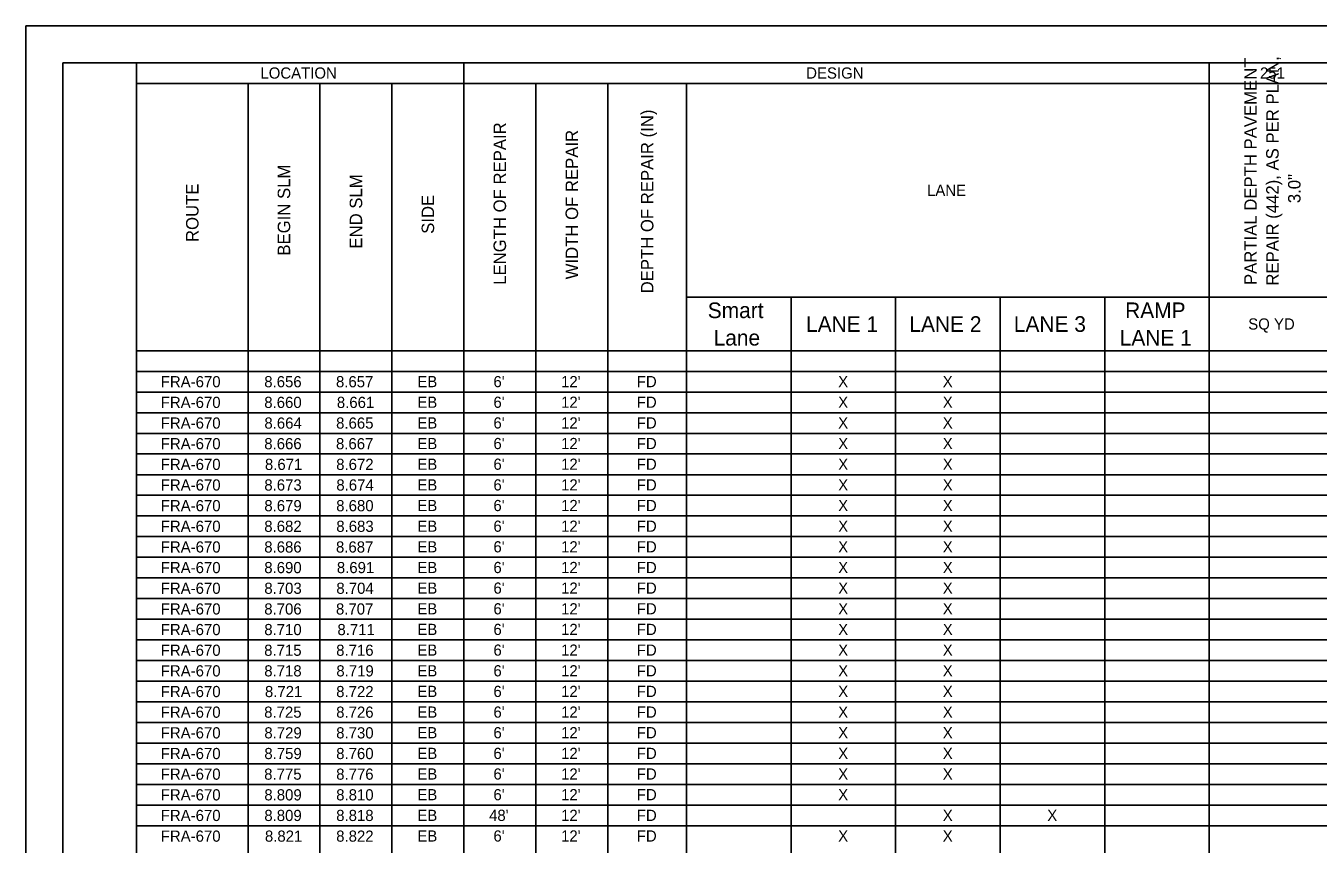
# Model space of a CAD drawing. Extents: x 0 to 34, y 0 to 22.
# Drawn here: x 0 to 17.5, y 10.92 to 22 of the extents above; entities that cross this region are included whole.
import ezdxf

# ---------------------------------------------------------------- set-up
doc = ezdxf.new("R2010")
doc.units = 0
for name, color, linetype in [('SH_Border', 7, 'Continuous'), ('SH_Cut_Line', 7, 'Continuous'), ('SH_Text', 7, 'Continuous')]:
    doc.layers.add(name, color=color, linetype=linetype)

msp = doc.modelspace()

# ---------------------------------------------------------------- linework, layer by layer
at = {"layer": 'SH_Border'}
for points in [[(0.5, 21.5), (1.5, 21.5), (1.5, 0.5), (0.5, 0.5)], [(1.5, 21.5), (33.5, 21.5), (33.5, 0.5), (1.5, 0.5)]]:
    msp.add_lwpolyline(points, close=True, dxfattribs=at)
at = {"layer": 'SH_Cut_Line'}
msp.add_lwpolyline([(0, 0), (34, 0), (34, 22), (0, 22)], close=True, dxfattribs=at)
at = {"layer": 'SH_Text'}
for p, q in [((1.5, 21.5), (32, 21.5)), ((5.931, 21.5), (5.931, 1.388)), ((16.024, 21.5), (16.024, 0.5)), ((1.5, 21.22), (32, 21.22)), ((1.5, 21.22), (1.5, 1.388)), ((3.008, 21.22), (3.008, 1.388)), ((3.982, 21.22), (3.982, 1.388)), ((4.956, 21.22), (4.956, 1.388)), ((6.905, 21.22), (6.905, 1.388)), ((7.879, 21.22), (7.879, 1.388)), ((8.946, 21.22), (8.946, 1.388)), ((8.946, 18.326), (23.028, 18.326)), ((10.361, 18.326), (10.361, 1.388)), ((11.777, 18.326), (11.777, 1.388)), ((13.193, 18.326), (13.193, 1.388)), ((14.608, 18.326), (14.608, 1.388)), ((1.5, 17.603), (32, 17.603)), ((1.5, 17.323), (32, 17.323)), ((1.5, 17.043), (32, 17.043)), ((1.5, 16.764), (32, 16.764)), ((1.5, 16.484), (32, 16.484)), ((1.5, 16.205), (32, 16.205)), ((1.5, 15.925), (32, 15.925)), ((1.5, 15.646), (32, 15.646)), ((1.5, 15.366), (32, 15.366)), ((1.5, 15.087), (32, 15.087)), ((1.5, 14.807), (32, 14.807)), ((1.5, 14.527), (32, 14.527)), ((1.5, 14.248), (32, 14.248)), ((1.5, 13.968), (32, 13.968)), ((1.5, 13.689), (32, 13.689)), ((1.5, 13.409), (32, 13.409)), ((1.5, 13.13), (32, 13.13)), ((1.5, 12.85), (32, 12.85)), ((1.5, 12.57), (32, 12.57)), ((1.5, 12.291), (32, 12.291)), ((1.5, 12.011), (32, 12.011)), ((1.5, 11.732), (32, 11.732)), ((1.5, 11.452), (32, 11.452)), ((1.5, 11.173), (32, 11.173))]:
    msp.add_line(p, q, dxfattribs=at)
for points in [[(1.5, 21.5), (1.5, 21.5), (1.5, 21.5), (1.5, 21.5)], [(1.5, 21.5), (1.5, 21.5), (1.5, 21.5), (1.5, 21.5)], [(1.5, 21.5), (1.5, 21.5), (1.5, 20.776), (1.5, 20.776)], [(1.5, 21.5), (1.5, 21.5), (1.5, 21.22), (1.5, 21.22)], [(1.5, 21.5), (1.5, 21.5), (1.5, 21.22), (1.5, 21.22)], [(1.5, 21.5), (1.5, 21.5), (1.5, 21.22), (1.5, 21.22)], [(1.5, 21.5), (1.5, 21.5), (1.5, 21.22), (1.5, 21.22)], [(1.5, 21.5), (1.5, 21.5), (1.5, 21.22), (1.5, 21.22)], [(1.5, 21.5), (1.5, 21.5), (1.5, 21.22), (1.5, 21.22)], [(1.5, 21.5), (1.5, 21.5), (1.5, 21.22), (1.5, 21.22)], [(1.5, 21.5), (1.5, 21.5), (1.5, 21.22), (1.5, 21.22)], [(1.5, 21.5), (1.5, 21.5), (1.5, 21.22), (1.5, 21.22)], [(1.5, 21.5), (1.5, 21.5), (1.5, 21.22), (1.5, 21.22)], [(1.5, 21.5), (1.5, 21.5), (1.5, 21.22), (1.5, 21.22)], [(1.5, 21.5), (1.5, 21.5), (1.5, 21.22), (1.5, 21.22)], [(1.5, 21.5), (1.5, 21.5), (1.5, 21.22), (1.5, 21.22)], [(1.5, 21.5), (1.5, 21.5), (1.5, 21.22), (1.5, 21.22)], [(1.5, 21.5), (1.5, 21.5), (1.5, 21.22), (1.5, 21.22)], [(1.5, 21.5), (1.5, 21.5), (1.5, 21.22), (1.5, 21.22)], [(1.5, 21.5), (1.5, 21.5), (1.5, 21.22), (1.5, 21.22)], [(1.5, 21.5), (1.5, 21.5), (1.5, 21.22), (1.5, 21.22)], [(1.5, 21.5), (1.5, 21.5), (1.5, 21.22), (1.5, 21.22)], [(1.5, 21.5), (1.5, 21.5), (1.5, 21.22), (1.5, 21.22)], [(1.5, 21.5), (1.5, 21.5), (1.5, 21.22), (1.5, 21.22)], [(1.5, 21.5), (1.5, 21.5), (1.5, 21.22), (1.5, 21.22)], [(1.5, 21.5), (1.5, 21.5), (1.5, 21.22), (1.5, 21.22)], [(1.5, 21.5), (1.5, 21.5), (1.5, 21.22), (1.5, 21.22)], [(1.5, 21.5), (1.5, 21.5), (1.5, 21.22), (1.5, 21.22)], [(1.5, 21.5), (1.5, 21.5), (1.5, 21.22), (1.5, 21.22)], [(1.5, 21.5), (1.5, 21.5), (1.5, 21.22), (1.5, 21.22)], [(1.5, 21.5), (1.5, 21.5), (1.5, 21.22), (1.5, 21.22)], [(1.5, 21.5), (1.5, 21.5), (1.5, 21.22), (1.5, 21.22)], [(1.5, 21.5), (1.5, 21.5), (1.5, 21.22), (1.5, 21.22)], [(1.5, 21.5), (1.5, 21.5), (1.5, 21.22), (1.5, 21.22)], [(1.5, 21.5), (1.5, 21.5), (1.5, 21.22), (1.5, 21.22)], [(1.5, 21.5), (1.5, 21.5), (1.5, 21.22), (1.5, 21.22)], [(1.5, 21.5), (1.5, 21.5), (1.5, 21.22), (1.5, 21.22)], [(1.5, 21.5), (1.5, 21.5), (1.5, 21.22), (1.5, 21.22)], [(1.5, 21.5), (1.5, 21.5), (1.5, 21.22), (1.5, 21.22)], [(1.5, 21.5), (1.5, 21.5), (1.5, 21.22), (1.5, 21.22)], [(1.5, 21.5), (1.5, 21.5), (1.5, 21.22), (1.5, 21.22)], [(1.5, 21.5), (1.5, 21.5), (1.5, 21.22), (1.5, 21.22)], [(1.5, 21.5), (1.5, 21.5), (1.5, 21.22), (1.5, 21.22)], [(1.5, 21.5), (1.5, 21.5), (1.5, 21.22), (1.5, 21.22)], [(1.5, 21.5), (1.5, 21.5), (1.5, 21.22), (1.5, 21.22)], [(1.5, 21.5), (1.5, 21.5), (1.5, 21.22), (1.5, 21.22)], [(1.5, 21.5), (1.5, 21.5), (1.5, 21.22), (1.5, 21.22)], [(1.5, 21.5), (1.5, 21.5), (1.5, 21.22), (1.5, 21.22)], [(1.5, 21.5), (1.5, 21.5), (1.5, 21.22), (1.5, 21.22)], [(1.5, 21.5), (1.5, 21.5), (1.5, 21.22), (1.5, 21.22)], [(1.5, 21.5), (1.5, 21.5), (1.5, 21.22), (1.5, 21.22)], [(1.5, 21.5), (1.5, 21.5), (1.5, 21.22), (1.5, 21.22)], [(1.5, 21.5), (1.5, 21.5), (1.5, 21.22), (1.5, 21.22)], [(1.5, 21.5), (1.5, 21.5), (1.5, 21.22), (1.5, 21.22)], [(1.5, 21.5), (1.5, 21.5), (1.5, 21.22), (1.5, 21.22)], [(1.5, 21.5), (1.5, 21.5), (1.5, 21.22), (1.5, 21.22)], [(1.5, 21.5), (1.5, 21.5), (1.5, 21.22), (1.5, 21.22)], [(1.5, 21.5), (1.5, 21.5), (1.5, 21.22), (1.5, 21.22)], [(1.5, 21.5), (1.5, 21.5), (1.5, 21.22), (1.5, 21.22)], [(1.5, 21.5), (1.5, 21.5), (1.5, 21.22), (1.5, 21.22)], [(1.5, 21.5), (1.5, 21.5), (1.5, 21.22), (1.5, 21.22)], [(1.5, 21.5), (1.5, 21.5), (1.5, 21.22), (1.5, 21.22)], [(1.5, 21.5), (1.5, 21.5), (1.5, 21.22), (1.5, 21.22)], [(1.5, 21.5), (1.5, 21.5), (1.5, 21.22), (1.5, 21.22)], [(1.5, 21.5), (1.5, 21.5), (1.5, 21.22), (1.5, 21.22)], [(1.5, 21.5), (1.5, 21.5), (1.5, 21.22), (1.5, 21.22)], [(1.5, 21.5), (1.5, 21.5), (1.5, 21.22), (1.5, 21.22)], [(1.5, 21.5), (1.5, 21.5), (1.5, 21.22), (1.5, 21.22)], [(1.5, 21.5), (1.5, 21.5), (1.5, 21.22), (1.5, 21.22)], [(1.5, 21.5), (1.5, 21.5), (1.5, 21.22), (1.5, 21.22)], [(1.5, 21.5), (1.5, 21.5), (1.5, 21.22), (1.5, 21.22)], [(1.5, 21.5), (1.5, 21.5), (1.5, 21.22), (1.5, 21.22)], [(1.5, 21.5), (1.5, 21.5), (1.5, 21.22), (1.5, 21.22)], [(1.5, 21.5), (1.5, 21.5), (1.5, 21.22), (1.5, 21.22)], [(1.5, 21.5), (1.5, 21.5), (1.5, 21.22), (1.5, 21.22)], [(1.5, 21.5), (1.5, 21.5), (1.5, 21.22), (1.5, 21.22)], [(1.5, 21.5), (1.5, 21.5), (1.5, 21.22), (1.5, 21.22)], [(1.5, 21.5), (1.5, 21.5), (1.5, 21.22), (1.5, 21.22)], [(1.5, 21.5), (1.5, 21.5), (1.5, 21.22), (1.5, 21.22)], [(1.5, 21.5), (1.5, 21.5), (1.5, 21.22), (1.5, 21.22)], [(1.5, 21.5), (1.5, 21.5), (1.5, 21.22), (1.5, 21.22)], [(1.5, 21.5), (1.5, 21.5), (1.5, 21.22), (1.5, 21.22)], [(1.5, 21.5), (1.5, 21.5), (1.5, 21.22), (1.5, 21.22)], [(1.5, 21.5), (1.5, 21.5), (1.5, 21.22), (1.5, 21.22)], [(1.5, 21.5), (1.5, 21.5), (1.5, 21.22), (1.5, 21.22)], [(1.5, 21.5), (1.5, 21.5), (1.5, 21.22), (1.5, 21.22)], [(1.5, 21.5), (1.5, 21.5), (1.5, 21.22), (1.5, 21.22)], [(1.5, 21.5), (1.5, 21.5), (1.5, 21.22), (1.5, 21.22)], [(1.5, 21.5), (1.5, 21.5), (1.5, 21.22), (1.5, 21.22)], [(1.5, 21.5), (1.5, 21.5), (1.5, 21.22), (1.5, 21.22)], [(1.5, 21.5), (1.5, 21.5), (1.5, 21.22), (1.5, 21.22)], [(1.5, 21.5), (1.5, 21.5), (1.5, 21.22), (1.5, 21.22)], [(1.5, 21.5), (1.5, 21.5), (1.5, 21.22), (1.5, 21.22)], [(1.5, 21.5), (1.5, 21.5), (1.5, 21.22), (1.5, 21.22)], [(1.5, 21.5), (1.5, 21.5), (1.5, 21.22), (1.5, 21.22)], [(1.5, 21.5), (1.5, 21.5), (1.5, 21.22), (1.5, 21.22)], [(1.5, 21.5), (1.5, 21.5), (1.5, 21.22), (1.5, 21.22)], [(1.5, 21.5), (1.5, 21.5), (1.5, 21.22), (1.5, 21.22)], [(1.5, 21.5), (1.5, 21.5), (1.5, 21.22), (1.5, 21.22)], [(1.5, 21.5), (1.5, 21.5), (1.5, 21.22), (1.5, 21.22)], [(1.5, 21.5), (1.5, 21.5), (1.5, 21.22), (1.5, 21.22)], [(1.5, 21.5), (1.5, 21.5), (1.5, 21.22), (1.5, 21.22)], [(1.5, 21.5), (1.5, 21.5), (1.5, 21.22), (1.5, 21.22)], [(1.5, 21.5), (1.5, 21.5), (1.5, 21.22), (1.5, 21.22)], [(1.5, 21.5), (1.5, 21.5), (1.5, 21.22), (1.5, 21.22)], [(1.5, 21.5), (1.5, 21.5), (1.5, 21.22), (1.5, 21.22)], [(1.5, 21.5), (1.5, 21.5), (1.5, 21.22), (1.5, 21.22)], [(1.5, 21.5), (1.5, 21.5), (1.5, 21.22), (1.5, 21.22)], [(1.5, 21.5), (1.5, 21.5), (1.5, 21.22), (1.5, 21.22)], [(1.5, 21.5), (1.5, 21.5), (1.5, 21.22), (1.5, 21.22)], [(1.5, 21.5), (1.5, 21.5), (1.5, 21.22), (1.5, 21.22)], [(1.5, 21.5), (1.5, 21.5), (1.5, 21.22), (1.5, 21.22)], [(1.5, 21.5), (1.5, 21.5), (1.5, 21.22), (1.5, 21.22)], [(1.5, 21.5), (1.5, 21.5), (1.5, 21.22), (1.5, 21.22)], [(1.5, 21.5), (1.5, 21.5), (1.5, 21.22), (1.5, 21.22)], [(1.5, 21.5), (1.5, 21.5), (1.5, 21.22), (1.5, 21.22)], [(1.5, 21.5), (1.5, 21.5), (1.5, 21.22), (1.5, 21.22)], [(1.5, 21.5), (1.5, 21.5), (1.5, 21.22), (1.5, 21.22)], [(1.5, 21.5), (1.5, 21.5), (1.5, 21.22), (1.5, 21.22)], [(1.5, 21.5), (1.5, 21.5), (1.5, 21.5), (1.5, 21.5)], [(1.5, 21.5), (1.5, 21.5), (1.5, 21.5), (1.5, 21.5)]]:
    msp.add_lwpolyline(points, close=True, dxfattribs=at)

# ---------------------------------------------------------------- texts
for s, height, p in [('PARTIAL DEPTH PAVEMENT ', 0.16914, (16.667, 18.492)), ('REPAIR (442), AS PER PLAN, ', 0.16914, (16.963, 18.484)), ('DEPTH OF REPAIR (IN)', 0.16914, (8.497, 18.379)), ('LENGTH OF REPAIR', 0.16914, (6.502, 18.495)), ('WIDTH OF REPAIR', 0.16914, (7.477, 18.569)), ('BEGIN SLM', 0.1691, (3.579, 18.89)), ('END SLM', 0.1691, (4.554, 18.985)), ('3.0"', 0.1691, (17.259, 19.6)), ('ROUTE', 0.1691, (2.338, 19.074)), ('SIDE', 0.1691, (5.528, 19.185))]:
    msp.add_text(s, height=height, rotation=90, dxfattribs=at).set_placement(p)
for s, height, p in [('LOCATION', 0.1513, (3.176, 21.286)), ('DESIGN', 0.1513, (10.566, 21.286)), ('251', 0.1513, (16.71, 21.286)), ('LANE', 0.1513, (12.202, 19.698)), ('Smart ', 0.2118, (9.233, 18.044)), ('RAMP ', 0.2118, (14.884, 18.044)), ('LANE 1', 0.2118, (10.564, 17.858)), ('LANE 2', 0.2118, (11.963, 17.858)), ('LANE 3', 0.2118, (13.377, 17.858)), ('SQ YD', 0.1513, (16.551, 17.889)), ('Lane', 0.2118, (9.312, 17.673)), ('LANE 1', 0.2118, (14.811, 17.673)), ('FRA-670', 0.1513, (1.827, 17.108)), ('8.656', 0.1513, (3.228, 17.108)), ('8.657', 0.1513, (4.199, 17.108)), ('EB', 0.1513, (5.301, 17.109)), ("6'", 0.1513, (6.331, 17.109)), ("12'", 0.1513, (7.247, 17.109)), ('FD', 0.1513, (8.272, 17.109)), ('X', 0.151, (10.999, 17.109)), ('X', 0.151, (12.415, 17.109)), ('FRA-670', 0.1513, (1.827, 16.828)), ('8.660', 0.1513, (3.228, 16.828)), ('8.661', 0.1513, (4.211, 16.828)), ('EB', 0.1513, (5.301, 16.83)), ("6'", 0.1513, (6.331, 16.83)), ("12'", 0.1513, (7.247, 16.83)), ('FD', 0.1513, (8.272, 16.83)), ('X', 0.151, (10.999, 16.83)), ('X', 0.151, (12.415, 16.83)), ('FRA-670', 0.1513, (1.827, 16.548)), ('8.664', 0.1513, (3.23, 16.548)), ('8.665', 0.1513, (4.201, 16.548)), ('EB', 0.1513, (5.301, 16.55)), ("6'", 0.1513, (6.331, 16.55)), ("12'", 0.1513, (7.247, 16.55)), ('FD', 0.1513, (8.272, 16.55)), ('X', 0.151, (10.999, 16.55)), ('X', 0.151, (12.415, 16.55)), ('FRA-670', 0.1513, (1.827, 16.269)), ('8.666', 0.1513, (3.228, 16.269)), ('8.667', 0.1513, (4.199, 16.269)), ('EB', 0.1513, (5.301, 16.271)), ("6'", 0.1513, (6.331, 16.271)), ("12'", 0.1513, (7.247, 16.271)), ('FD', 0.1513, (8.272, 16.271)), ('X', 0.151, (10.999, 16.271)), ('X', 0.151, (12.415, 16.271)), ('FRA-670', 0.1513, (1.827, 15.989)), ('8.671', 0.1513, (3.237, 15.989)), ('8.672', 0.1513, (4.202, 15.989)), ('EB', 0.1513, (5.301, 15.991)), ("6'", 0.1513, (6.331, 15.991)), ("12'", 0.1513, (7.247, 15.991)), ('FD', 0.1513, (8.272, 15.991)), ('X', 0.151, (10.999, 15.991)), ('X', 0.151, (12.415, 15.991)), ('FRA-670', 0.1513, (1.827, 15.71)), ('8.673', 0.1513, (3.229, 15.71)), ('8.674', 0.1513, (4.204, 15.71)), ('EB', 0.1513, (5.301, 15.711)), ("6'", 0.1513, (6.331, 15.711)), ("12'", 0.1513, (7.247, 15.711)), ('FD', 0.1513, (8.272, 15.711)), ('X', 0.151, (10.999, 15.711)), ('X', 0.151, (12.415, 15.711)), ('FRA-670', 0.1513, (1.827, 15.43)), ('8.679', 0.1513, (3.229, 15.43)), ('8.680', 0.1513, (4.202, 15.43)), ('EB', 0.1513, (5.301, 15.432)), ("6'", 0.1513, (6.331, 15.432)), ("12'", 0.1513, (7.247, 15.432)), ('FD', 0.1513, (8.272, 15.432)), ('X', 0.151, (10.999, 15.432)), ('X', 0.151, (12.415, 15.432)), ('FRA-670', 0.1513, (1.827, 15.151)), ('8.682', 0.1513, (3.228, 15.151)), ('8.683', 0.1513, (4.203, 15.151)), ('EB', 0.1513, (5.301, 15.152)), ("6'", 0.1513, (6.331, 15.152)), ("12'", 0.1513, (7.247, 15.152)), ('FD', 0.1513, (8.272, 15.152)), ('X', 0.151, (10.999, 15.152)), ('X', 0.151, (12.415, 15.152)), ('FRA-670', 0.1513, (1.827, 14.871)), ('8.686', 0.1513, (3.228, 14.871)), ('8.687', 0.1513, (4.199, 14.871)), ('EB', 0.1513, (5.301, 14.873)), ("6'", 0.1513, (6.331, 14.873)), ("12'", 0.1513, (7.247, 14.873)), ('FD', 0.1513, (8.272, 14.873)), ('X', 0.151, (10.999, 14.873)), ('X', 0.151, (12.415, 14.873)), ('FRA-670', 0.1513, (1.827, 14.592)), ('8.690', 0.1513, (3.228, 14.592)), ('8.691', 0.1513, (4.211, 14.592)), ('EB', 0.1513, (5.301, 14.593)), ("6'", 0.1513, (6.331, 14.593)), ("12'", 0.1513, (7.247, 14.593)), ('FD', 0.1513, (8.272, 14.593)), ('X', 0.151, (10.999, 14.593)), ('X', 0.151, (12.415, 14.593)), ('FRA-670', 0.1513, (1.827, 14.312)), ('8.703', 0.1513, (3.229, 14.312)), ('8.704', 0.1513, (4.204, 14.312)), ('EB', 0.1513, (5.301, 14.314)), ("6'", 0.1513, (6.331, 14.314)), ("12'", 0.1513, (7.247, 14.314)), ('FD', 0.1513, (8.272, 14.314)), ('X', 0.151, (10.999, 14.314)), ('X', 0.151, (12.415, 14.314)), ('FRA-670', 0.1513, (1.827, 14.032)), ('8.706', 0.1513, (3.228, 14.032)), ('8.707', 0.1513, (4.199, 14.032)), ('EB', 0.1513, (5.301, 14.034)), ("6'", 0.1513, (6.331, 14.034)), ("12'", 0.1513, (7.247, 14.034)), ('FD', 0.1513, (8.272, 14.034)), ('X', 0.151, (10.999, 14.034)), ('X', 0.151, (12.415, 14.034)), ('FRA-670', 0.1513, (1.827, 13.753)), ('8.710', 0.1513, (3.228, 13.753)), ('8.711', 0.1513, (4.219, 13.753)), ('EB', 0.1513, (5.301, 13.755)), ("6'", 0.1513, (6.331, 13.755)), ("12'", 0.1513, (7.247, 13.755)), ('FD', 0.1513, (8.272, 13.755)), ('X', 0.151, (10.999, 13.755)), ('X', 0.151, (12.415, 13.755)), ('FRA-670', 0.1513, (1.827, 13.473)), ('8.715', 0.1513, (3.227, 13.473)), ('8.716', 0.1513, (4.202, 13.473)), ('EB', 0.1513, (5.301, 13.475)), ("6'", 0.1513, (6.331, 13.475)), ("12'", 0.1513, (7.247, 13.475)), ('FD', 0.1513, (8.272, 13.475)), ('X', 0.151, (10.999, 13.475)), ('X', 0.151, (12.415, 13.475)), ('FRA-670', 0.1513, (1.827, 13.194)), ('8.718', 0.1513, (3.228, 13.194)), ('8.719', 0.1513, (4.204, 13.194)), ('EB', 0.1513, (5.301, 13.195)), ("6'", 0.1513, (6.331, 13.195)), ("12'", 0.1513, (7.247, 13.195)), ('FD', 0.1513, (8.272, 13.195)), ('X', 0.151, (10.999, 13.195)), ('X', 0.151, (12.415, 13.195)), ('FRA-670', 0.1513, (1.827, 12.914)), ('8.721', 0.1513, (3.237, 12.914)), ('8.722', 0.1513, (4.202, 12.914)), ('EB', 0.1513, (5.301, 12.916)), ("6'", 0.1513, (6.331, 12.916)), ("12'", 0.1513, (7.247, 12.916)), ('FD', 0.1513, (8.272, 12.916)), ('X', 0.151, (10.999, 12.916)), ('X', 0.151, (12.415, 12.916)), ('FRA-670', 0.1513, (1.827, 12.635)), ('8.725', 0.1513, (3.227, 12.635)), ('8.726', 0.1513, (4.202, 12.635)), ('EB', 0.1513, (5.301, 12.636)), ("6'", 0.1513, (6.331, 12.636)), ("12'", 0.1513, (7.247, 12.636)), ('FD', 0.1513, (8.272, 12.636)), ('X', 0.151, (10.999, 12.636)), ('X', 0.151, (12.415, 12.636)), ('FRA-670', 0.1513, (1.827, 12.355)), ('8.729', 0.1513, (3.229, 12.355)), ('8.730', 0.1513, (4.202, 12.355)), ('EB', 0.1513, (5.301, 12.357)), ("6'", 0.1513, (6.331, 12.357)), ("12'", 0.1513, (7.247, 12.357)), ('FD', 0.1513, (8.272, 12.357)), ('X', 0.151, (10.999, 12.357)), ('X', 0.151, (12.415, 12.357)), ('FRA-670', 0.1513, (1.827, 12.075)), ('8.759', 0.1513, (3.229, 12.075)), ('8.760', 0.1513, (4.202, 12.075)), ('EB', 0.1513, (5.301, 12.077)), ("6'", 0.1513, (6.331, 12.077)), ("12'", 0.1513, (7.247, 12.077)), ('FD', 0.1513, (8.272, 12.077)), ('X', 0.151, (10.999, 12.077)), ('X', 0.151, (12.415, 12.077)), ('FRA-670', 0.1513, (1.827, 11.796)), ('8.775', 0.1513, (3.227, 11.796)), ('8.776', 0.1513, (4.202, 11.796)), ('EB', 0.1513, (5.301, 11.798)), ("6'", 0.1513, (6.331, 11.798)), ("12'", 0.1513, (7.247, 11.798)), ('FD', 0.1513, (8.272, 11.798)), ('X', 0.151, (10.999, 11.798)), ('X', 0.151, (12.415, 11.798)), ('FRA-670', 0.1513, (1.827, 11.516)), ('8.809', 0.1513, (3.229, 11.516)), ('8.810', 0.1513, (4.202, 11.516)), ('EB', 0.1513, (5.301, 11.518)), ("6'", 0.1513, (6.331, 11.518)), ("12'", 0.1513, (7.247, 11.518)), ('FD', 0.1513, (8.272, 11.518)), ('X', 0.151, (10.999, 11.518)), ('FRA-670', 0.1513, (1.827, 11.237)), ('8.809', 0.1513, (3.229, 11.237)), ('8.818', 0.1513, (4.202, 11.237)), ('EB', 0.1513, (5.301, 11.238)), ("48'", 0.1513, (6.272, 11.238)), ("12'", 0.1513, (7.247, 11.238)), ('FD', 0.1513, (8.272, 11.238)), ('X', 0.151, (12.415, 11.238)), ('X', 0.151, (13.83, 11.238)), ('FRA-670', 0.1513, (1.827, 10.957)), ('8.821', 0.1513, (3.237, 10.957)), ('8.822', 0.1513, (4.202, 10.957)), ('EB', 0.1513, (5.301, 10.959)), ("6'", 0.1513, (6.331, 10.959)), ("12'", 0.1513, (7.247, 10.959)), ('FD', 0.1513, (8.272, 10.959)), ('X', 0.151, (10.999, 10.959)), ('X', 0.151, (12.415, 10.959))]:
    msp.add_text(s, height=height, dxfattribs=at).set_placement(p)

doc.saveas('drawing.dxf')
